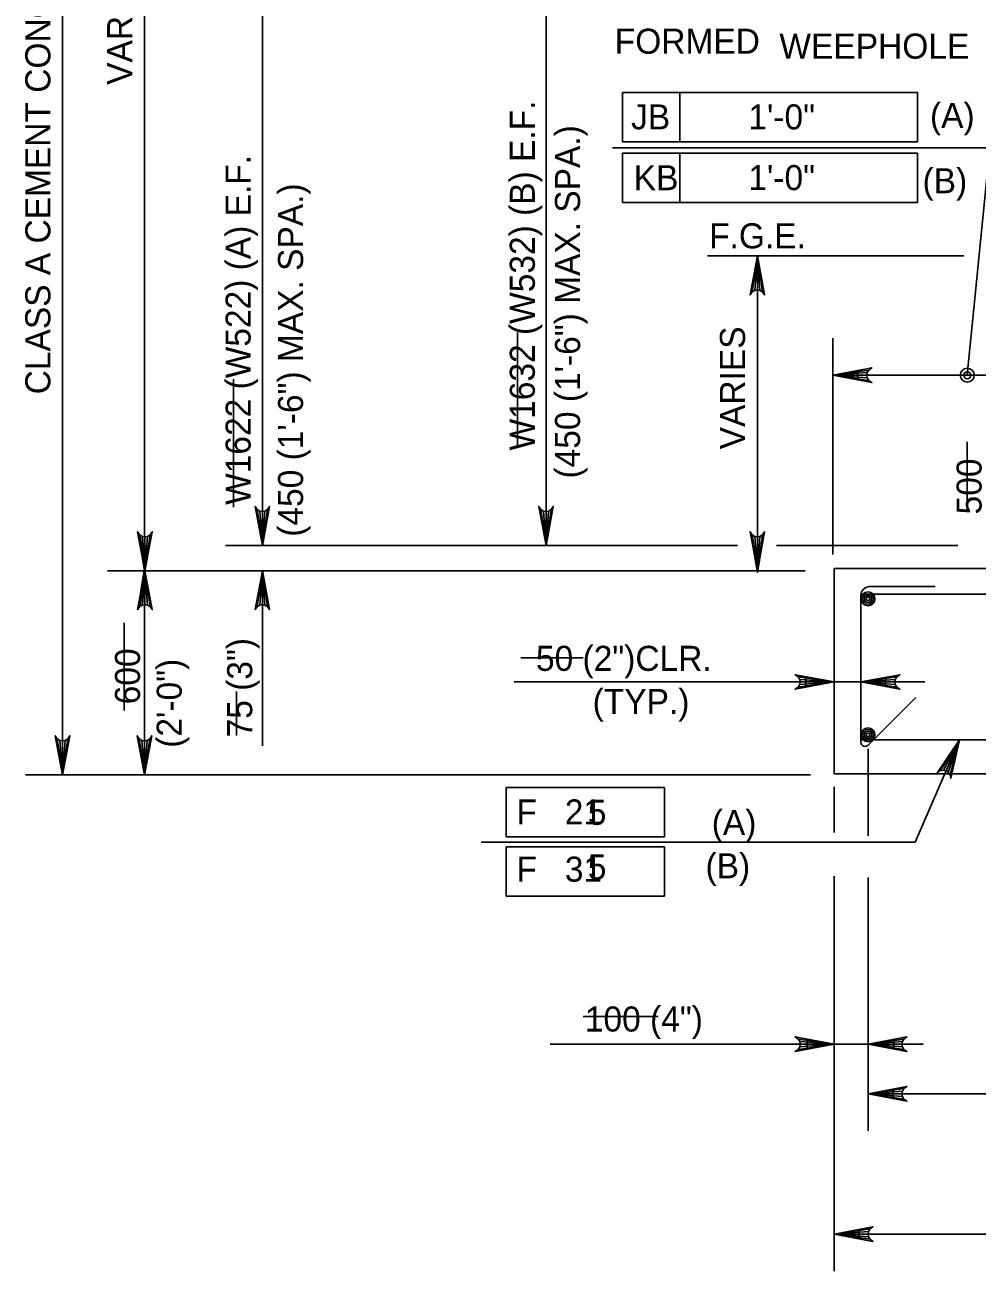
# Model space of a CAD drawing. Extents: x 179 to 454, y -271 to 54.
# Drawn here: x 266.44 to 271, y -54.96 to -48.99 of the extents above; entities that cross this region are included whole.
import ezdxf

# ---------------------------------------------------------------- set-up
doc = ezdxf.new("R2010")
doc.units = 0
for name, color, linetype in [('Level 3', 7, 'Continuous'), ('Level 4', 7, 'Continuous'), ('Level 41', 7, 'Continuous'), ('Level 5', 7, 'Continuous'), ('Level 6', 7, 'Continuous'), ('Level 9', 7, 'Continuous')]:
    doc.layers.add(name, color=color, linetype=linetype)

msp = doc.modelspace()

# ---------------------------------------------------------------- linework, layer by layer
at = {"layer": 'Level 3'}
msp.add_line((270.7016, -52.901), (270.9129, -52.4105), dxfattribs=at)
msp.add_lwpolyline([(270.9129, -52.4105), (270.8713, -52.5955), (270.8678, -52.5784), (270.8593, -52.5667), (270.8487, -52.5598), (270.8363, -52.5568), (270.8219, -52.5586), (270.8071, -52.5679), (270.9129, -52.4105), (270.8219, -52.5586), (270.8363, -52.5568), (270.9129, -52.4105), (270.8487, -52.5598), (270.8593, -52.5667), (270.9129, -52.4105), (270.8678, -52.5784)], dxfattribs=at)
at = {"layer": 'Level 4'}
for p, q in [((266.6172, -52.5784), (266.6172, -46.1096)), ((268.9329, -51.4797), (268.9329, -48.1905)), ((267.5743, -51.4797), (267.5743, -48.7387)), ((267.0101, -51.483), (267.0101, -48.8553)), ((269.2998, -49.3098), (270.7118, -49.3098)), ((269.2998, -49.5461), (269.2998, -49.3098)), ((269.5737, -49.5461), (269.5737, -49.3098)), ((270.7118, -49.3098), (270.7118, -49.5461)), ((270.7118, -49.5461), (269.2998, -49.5461)), ((269.2521, -49.575), (271.0588, -49.575)), ((269.2998, -49.6013), (270.7118, -49.6013)), ((269.2998, -49.8375), (269.2998, -49.6013)), ((269.5737, -49.8375), (269.5737, -49.6013)), ((270.7118, -49.6013), (270.7118, -49.8375)), ((271.0588, -49.575), (270.9504, -50.6645)), ((270.7118, -49.8375), (269.2998, -49.8375)), ((270.9339, -50.093), (269.7062, -50.093)), ((269.9451, -51.6011), (269.9451, -50.093)), ((270.307, -51.5236), (270.307, -50.4873)), ((270.307, -50.6645), (271.5428, -50.6645)), ((269.8506, -51.4797), (267.3971, -51.4798)), ((269.7649, -51.4797), (268.5564, -51.4797)), ((270.9045, -51.4797), (270.0365, -51.4797)), ((270.8169, -51.4797), (270.0937, -51.4797)), ((270.1742, -51.6011), (266.8329, -51.6011)), ((268.8272, -51.6011), (267.3971, -51.6011)), ((267.5743, -51.6011), (267.5743, -52.4394)), ((267.0101, -52.5784), (267.0101, -51.7086)), ((267.5743, -51.7192), (267.5743, -51.8373)), ((270.4411, -52.1341), (268.7799, -52.1341)), ((270.4411, -52.1341), (270.747, -52.1341)), ((270.4751, -52.4539), (270.4751, -52.8712)), ((270.4751, -52.4592), (270.4751, -52.7449)), ((267.2378, -52.5784), (266.44, -52.5784)), ((266.7242, -52.5784), (270.199, -52.5784)), ((268.7417, -52.8761), (268.7417, -52.6399)), ((268.7417, -52.6399), (269.4996, -52.6399)), ((269.4996, -52.6399), (269.4996, -52.8761)), ((270.3125, -52.6359), (270.3125, -52.8549)), ((269.4996, -52.8761), (268.7417, -52.8761)), ((268.623, -52.901), (270.7016, -52.901)), ((268.7417, -52.9244), (269.4996, -52.9244)), ((268.7417, -53.1607), (268.7417, -52.9244)), ((269.4996, -52.9244), (269.4996, -53.1607)), ((270.3125, -53.0648), (270.3125, -54.9564)), ((270.4751, -53.0709), (270.4751, -54.2843)), ((269.4996, -53.1607), (268.7417, -53.1607)), ((270.3125, -53.8698), (268.9532, -53.8698)), ((270.3125, -53.8698), (270.7387, -53.8698)), ((270.4752, -54.1072), (274.7208, -54.1072)), ((270.3125, -54.7792), (274.8834, -54.7792))]:
    msp.add_line(p, q, dxfattribs=at)
for points in [[(269.9451, -50.093), (269.98, -50.2794), (269.9701, -50.2651), (269.9576, -50.2577), (269.9451, -50.2555), (269.9326, -50.2577), (269.9201, -50.2651), (269.9102, -50.2794), (269.9451, -50.093), (269.9201, -50.2651), (269.9326, -50.2577), (269.9451, -50.093), (269.9451, -50.2555), (269.9576, -50.2577), (269.9451, -50.093), (269.9701, -50.2651)], [(270.307, -50.6645), (270.4934, -50.6296), (270.4791, -50.6395), (270.4717, -50.652), (270.4695, -50.6645), (270.4717, -50.677), (270.4791, -50.6895), (270.4934, -50.6994), (270.307, -50.6645), (270.4791, -50.6895), (270.4717, -50.677), (270.307, -50.6645), (270.4695, -50.6645), (270.4717, -50.652), (270.307, -50.6645), (270.4791, -50.6395)], [(267.5743, -51.4797), (267.5393, -51.2933), (267.5492, -51.3077), (267.5618, -51.3151), (267.5743, -51.3173), (267.5867, -51.3151), (267.5992, -51.3077), (267.6092, -51.2933), (267.5743, -51.4797), (267.5992, -51.3077), (267.5867, -51.3151), (267.5743, -51.4797), (267.5743, -51.3173), (267.5618, -51.3151), (267.5743, -51.4797), (267.5492, -51.3077)], [(268.9329, -51.4797), (268.898, -51.2933), (268.9079, -51.3077), (268.9204, -51.3151), (268.9329, -51.3173), (268.9454, -51.3151), (268.9579, -51.3077), (268.9678, -51.2933), (268.9329, -51.4797), (268.9579, -51.3077), (268.9454, -51.3151), (268.9329, -51.4797), (268.9329, -51.3173), (268.9204, -51.3151), (268.9329, -51.4797), (268.9079, -51.3077)], [(267.0118, -51.6011), (267.0468, -51.4147), (267.0368, -51.429), (267.0243, -51.4364), (267.0118, -51.4386), (266.9993, -51.4364), (266.9868, -51.429), (266.9769, -51.4147), (267.0118, -51.6011), (266.9868, -51.429), (266.9993, -51.4364), (267.0118, -51.6011), (267.0118, -51.4386), (267.0243, -51.4364), (267.0118, -51.6011), (267.0368, -51.429)], [(269.9451, -51.6011), (269.9102, -51.4147), (269.9201, -51.429), (269.9326, -51.4364), (269.9451, -51.4386), (269.9576, -51.4364), (269.9701, -51.429), (269.98, -51.4147), (269.9451, -51.6011), (269.9701, -51.429), (269.9576, -51.4364), (269.9451, -51.6011), (269.9451, -51.4386), (269.9326, -51.4364), (269.9451, -51.6011), (269.9201, -51.429)], [(267.0118, -51.6011), (267.0468, -51.7875), (267.0368, -51.7732), (267.0243, -51.7657), (267.0118, -51.7636), (266.9993, -51.7657), (266.9868, -51.7732), (266.9769, -51.7875), (267.0118, -51.6011), (266.9868, -51.7732), (266.9993, -51.7657), (267.0118, -51.6011), (267.0118, -51.7636), (267.0243, -51.7657), (267.0118, -51.6011), (267.0368, -51.7732)], [(267.5743, -51.6011), (267.6092, -51.7875), (267.5992, -51.7732), (267.5867, -51.7657), (267.5743, -51.7636), (267.5618, -51.7657), (267.5492, -51.7732), (267.5393, -51.7875), (267.5743, -51.6011), (267.5492, -51.7732), (267.5618, -51.7657), (267.5743, -51.6011), (267.5743, -51.7636), (267.5867, -51.7657), (267.5743, -51.6011), (267.5992, -51.7732)], [(270.3125, -52.1341), (270.1261, -52.169), (270.1404, -52.1591), (270.1478, -52.1466), (270.15, -52.1341), (270.1478, -52.1216), (270.1404, -52.1091), (270.1261, -52.0992), (270.3125, -52.1341), (270.1404, -52.1091), (270.1478, -52.1216), (270.3125, -52.1341), (270.15, -52.1341), (270.1478, -52.1466), (270.3125, -52.1341), (270.1404, -52.1591)], [(270.4411, -52.1341), (270.6275, -52.0992), (270.6132, -52.1091), (270.6058, -52.1216), (270.6036, -52.1341), (270.6058, -52.1466), (270.6132, -52.1591), (270.6275, -52.169), (270.4411, -52.1341), (270.6132, -52.1591), (270.6058, -52.1466), (270.4411, -52.1341), (270.6036, -52.1341), (270.6058, -52.1216), (270.4411, -52.1341), (270.6132, -52.1091)], [(266.6172, -52.5784), (266.5822, -52.392), (266.5922, -52.4063), (266.6047, -52.4138), (266.6172, -52.4159), (266.6297, -52.4138), (266.6422, -52.4063), (266.6521, -52.392), (266.6172, -52.5784), (266.6422, -52.4063), (266.6297, -52.4138), (266.6172, -52.5784), (266.6172, -52.4159), (266.6047, -52.4138), (266.6172, -52.5784), (266.5922, -52.4063)], [(267.0101, -52.5784), (266.9752, -52.392), (266.9851, -52.4063), (266.9976, -52.4138), (267.0101, -52.4159), (267.0226, -52.4138), (267.0351, -52.4063), (267.045, -52.392), (267.0101, -52.5784), (267.0351, -52.4063), (267.0226, -52.4138), (267.0101, -52.5784), (267.0101, -52.4159), (266.9976, -52.4138), (267.0101, -52.5784), (266.9851, -52.4063)], [(270.3125, -53.8698), (270.1261, -53.9047), (270.1404, -53.8948), (270.1478, -53.8823), (270.15, -53.8698), (270.1478, -53.8573), (270.1404, -53.8448), (270.1261, -53.8349), (270.3125, -53.8698), (270.1404, -53.8448), (270.1478, -53.8573), (270.3125, -53.8698), (270.15, -53.8698), (270.1478, -53.8823), (270.3125, -53.8698), (270.1404, -53.8948)], [(270.4752, -53.8698), (270.6616, -53.8349), (270.6472, -53.8448), (270.6398, -53.8573), (270.6377, -53.8698), (270.6398, -53.8823), (270.6472, -53.8948), (270.6616, -53.9047), (270.4752, -53.8698), (270.6472, -53.8948), (270.6398, -53.8823), (270.4752, -53.8698), (270.6377, -53.8698), (270.6398, -53.8573), (270.4752, -53.8698), (270.6472, -53.8448)], [(270.4752, -54.1072), (270.6616, -54.0722), (270.6472, -54.0822), (270.6398, -54.0947), (270.6377, -54.1072), (270.6398, -54.1197), (270.6472, -54.1322), (270.6616, -54.1421), (270.4752, -54.1072), (270.6472, -54.1322), (270.6398, -54.1197), (270.4752, -54.1072), (270.6377, -54.1072), (270.6398, -54.0947), (270.4752, -54.1072), (270.6472, -54.0822)], [(270.3125, -54.7792), (270.4989, -54.7443), (270.4846, -54.7542), (270.4772, -54.7667), (270.475, -54.7792), (270.4772, -54.7918), (270.4846, -54.8042), (270.4989, -54.8142), (270.3125, -54.7792), (270.4846, -54.8042), (270.4772, -54.7918), (270.3125, -54.7792), (270.475, -54.7792), (270.4772, -54.7667), (270.3125, -54.7792), (270.4846, -54.7542)]]:
    msp.add_lwpolyline(points, dxfattribs=at)
for points in [[(269.9647, -50.2093), (269.9253, -50.2093), (269.9451, -50.0912)], [(270.4251, -50.6842), (270.4251, -50.6448), (270.307, -50.6645)], [(267.5546, -51.3617), (267.594, -51.3617), (267.5743, -51.4797)], [(268.9132, -51.3617), (268.9526, -51.3617), (268.9329, -51.4797)], [(267.0297, -51.483), (266.9904, -51.483), (267.0101, -51.6011)], [(269.9647, -51.4907), (269.9253, -51.4907), (269.9451, -51.6088)], [(267.0297, -51.7086), (266.9904, -51.7086), (267.0101, -51.5905)], [(267.5546, -51.7192), (267.594, -51.7192), (267.5743, -51.6011)], [(270.178, -52.1144), (270.178, -52.1537), (270.2962, -52.1341)], [(270.5592, -52.1537), (270.5592, -52.1144), (270.4411, -52.1341)], [(267.0297, -52.4603), (266.9904, -52.4603), (267.0101, -52.5784)], [(270.1834, -53.8501), (270.1834, -53.8895), (270.3016, -53.8698)], [(270.5987, -53.8895), (270.5987, -53.8501), (270.4806, -53.8698)], [(270.5933, -54.0875), (270.5933, -54.1268), (270.4752, -54.1072)], [(270.4306, -54.7596), (270.4306, -54.7989), (270.3125, -54.7792)]]:
    msp.add_lwpolyline(points, close=True, dxfattribs=at)
at = {"layer": 'Level 41'}
for p, q in [((268.7967, -51.013), (268.7967, -50.4592)), ((267.4358, -51.2973), (267.4358, -50.6837)), ((270.9503, -51.3123), (270.9503, -50.983)), ((266.9123, -52.2701), (266.9123, -51.8511)), ((268.812, -52.0187), (269.1111, -52.0187)), ((267.4507, -52.3898), (267.4507, -52.1803)), ((269.1107, -53.7362), (269.4697, -53.7362))]:
    msp.add_line(p, q, dxfattribs=at)
at = {"layer": 'Level 5'}
for radius in [0.0333, 0.0167]:
    msp.add_circle((270.9504, -50.6645), radius, dxfattribs=at)
at = {"layer": 'Level 6'}
for p, q in [((270.7962, -51.6774), (270.4821, -51.6774)), ((270.4411, -52.422), (270.4411, -51.7184)), ((274.7546, -51.7132), (270.4414, -51.7132)), ((270.7043, -52.2083), (270.4761, -52.4365)), ((270.4411, -52.4105), (274.7549, -52.4105))]:
    msp.add_line(p, q, dxfattribs=at)
for centre, radius in [((270.4751, -51.736), 0.0333), ((270.4751, -51.736), 0.025), ((270.4751, -51.736), 0.0167), ((270.4751, -51.736), 0.00833), ((270.4751, -52.3871), 0.0333), ((270.4751, -52.3871), 0.025), ((270.4751, -52.3871), 0.0167), ((270.4751, -52.3871), 0.00833)]:
    msp.add_circle(centre, radius, dxfattribs=at)
for centre, radius, start, end in [((270.4821, -51.7184), 0.041, 90, 180), ((270.4615, -52.422), 0.0205, 180, 315)]:
    msp.add_arc(centre, radius, start, end, dxfattribs=at)
at = {"layer": 'Level 9'}
for p, q in [((271.5428, -51.5902), (270.3125, -51.5902)), ((270.3125, -51.5902), (270.3125, -52.5744)), ((270.3125, -52.5744), (274.8834, -52.5744))]:
    msp.add_line(p, q, dxfattribs=at)

# ---------------------------------------------------------------- texts
at = {"layer": 'Level 3'}
for s, p in [('FORMED', (269.2621, -49.1241)), ('50 (2")CLR.', (268.8847, -52.0808)), ('100 (4")', (269.1189, -53.8088))]:
    msp.add_text(s, height=0.12, dxfattribs=at).set_placement(p)
for s, p in [('500', (271.0191, -51.3312)), ('75 (3")', (267.5258, -52.3996)), ('600', (266.9884, -52.241)), ('(2\'-0")', (267.1884, -52.4493))]:
    msp.add_text(s, height=0.12, rotation=90, dxfattribs=at).set_placement(p)
at = {"layer": 'Level 4'}
for s, p in [('CLASS A CEMENT CONCRETE', (266.5591, -50.7558)), ('VARIES', (266.9509, -49.2731)), ('W1632 (W532) (B) E.F.', (268.8794, -51.0249)), ('(450 (1\'-6") MAX. SPA.)', (269.096, -51.1593)), ('W1622 (W522) (A) E.F.', (267.5182, -51.2856)), ('(450 (1\'-6") MAX. SPA.)', (267.7695, -51.4382)), ('VARIES', (269.8859, -51.0194))]:
    msp.add_text(s, height=0.12, rotation=90, dxfattribs=at).set_placement(p)
for s, p in [('WEEPHOLE', (270.0507, -49.1477)), ('JB', (269.3403, -49.4866)), ('(A)', (270.7719, -49.4797)), ('KB', (269.353, -49.7781)), ('(B)', (270.7362, -49.7925)), ('F.G.E.', (269.714, -50.0567)), ('(TYP.)', (269.1562, -52.2877)), ('F   21', (268.7912, -52.8167)), ('(A)', (269.7265, -52.8672)), ('(B)', (269.6968, -53.0746)), ('F   31', (268.7912, -53.0907))]:
    msp.add_text(s, height=0.12, dxfattribs=at).set_placement(p)
at = {"layer": 'Level 41'}
for s, p in [('1\'-0"', (269.9017, -49.4866)), ('1\'-0"', (269.9017, -49.7776)), ('5', (269.133, -52.8185)), ('5', (269.133, -53.0804))]:
    msp.add_text(s, height=0.12, dxfattribs=at).set_placement(p)

doc.saveas('drawing.dxf')
